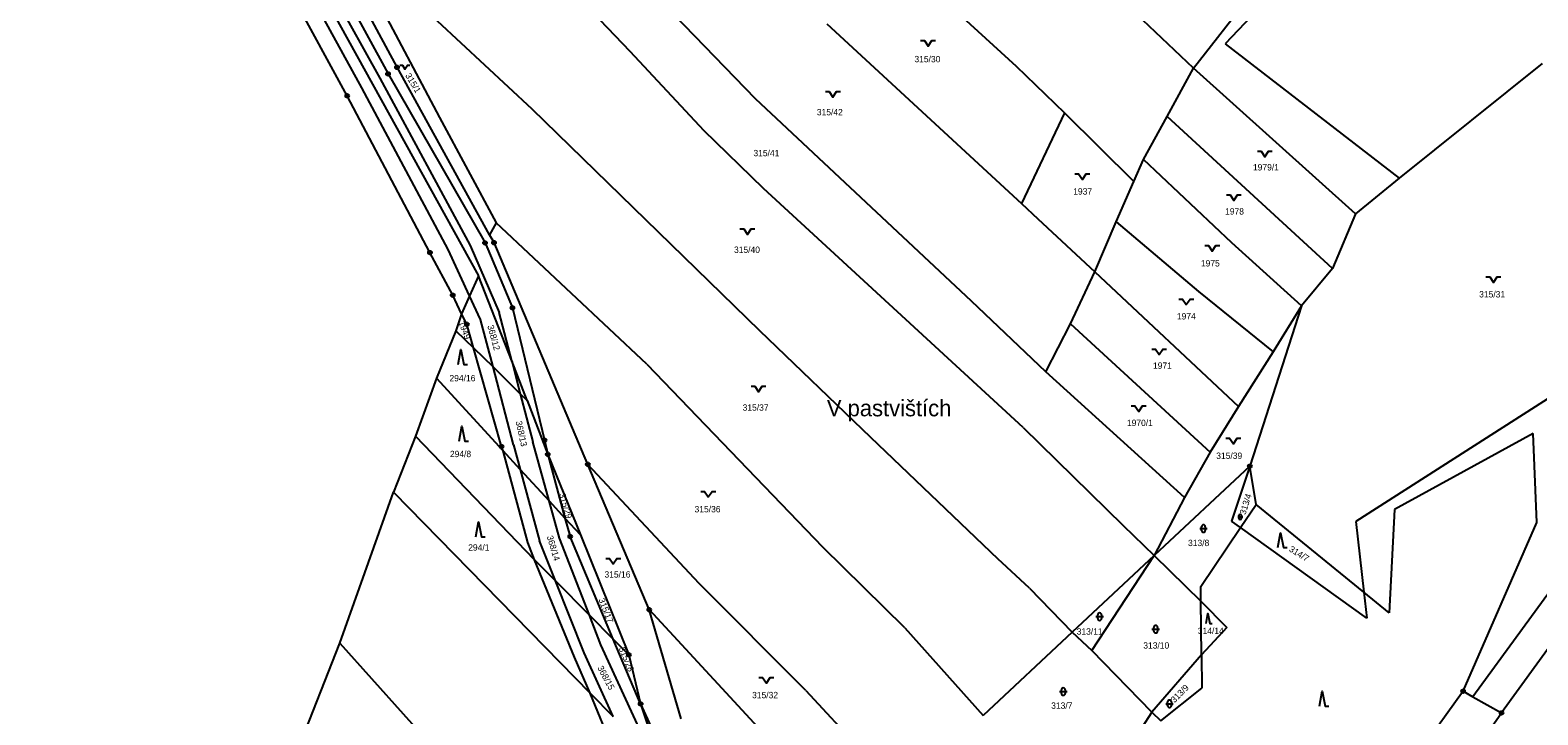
# Model space of a CAD drawing. Extents: x -762263 to -760336, y -1154405 to -1152076.
# Drawn here: x -761266.3 to -760862.4, y -1153501.2 to -1153317.8 of the extents above; entities that cross this region are included whole.
import ezdxf

# ---------------------------------------------------------------- set-up
doc = ezdxf.new("R2010")
doc.units = 0
for name, color, linetype in [('Vrstva 1', 7, 'Continuous'), ('Vrstva 15', 7, 'Continuous'), ('Vrstva 18', 7, 'Continuous'), ('Vrstva 24', 7, 'Continuous'), ('Vrstva 25', 7, 'Continuous'), ('Vrstva 4', 7, 'Continuous'), ('Vrstva 6', 7, 'Continuous')]:
    doc.layers.add(name, color=color, linetype=linetype)

msp = doc.modelspace()

# ---------------------------------------------------------------- linework, layer by layer
at = {"layer": 'Vrstva 1'}
for p, q in [((-761266.33, -1153166.38), (-761146.19, -1153383.6)), ((-761181.37, -1153335.36), (-761215.48, -1153272.86)), ((-761168.04, -1153327.74), (-761178.87, -1153307.53)), ((-761181.49, -1153309.12), (-761170.44, -1153329.52)), ((-760742.25, -1153321.15), (-760872.1, -1153500.69)), ((-761143.22, -1153372.6), (-761168.04, -1153327.74)), ((-761170.44, -1153329.52), (-761144.46, -1153374.78)), ((-761159.21, -1153377.37), (-761181.37, -1153335.36)), ((-761144.46, -1153374.78), (-761137.12, -1153392.18)), ((-761142.05, -1153374.72), (-761143.22, -1153372.6)), ((-761116.92, -1153434.11), (-761142.05, -1153374.72)), ((-761153.12, -1153388.8), (-761159.21, -1153377.37)), ((-761146.19, -1153383.6), (-761148.59, -1153388.96)), ((-761137.3, -1153406.37), (-761146.19, -1153383.6)), ((-761150.75, -1153393.78), (-761153.12, -1153388.8)), ((-761148.59, -1153388.96), (-761150.75, -1153393.78)), ((-761137.12, -1153392.18), (-761128.5, -1153427.63)), ((-761149.31, -1153396.6), (-761150.75, -1153393.78)), ((-761147.54, -1153402.91), (-761149.31, -1153396.6)), ((-761140.04, -1153429.35), (-761147.54, -1153402.91)), ((-761147.54, -1153402.91), (-761142.31, -1153408.03)), ((-761142.31, -1153408.03), (-761135.01, -1153415.18)), ((-761133.14, -1153417.01), (-761137.3, -1153406.37)), ((-761135.01, -1153415.18), (-761133.14, -1153417.01)), ((-761133.14, -1153417.01), (-761127.65, -1153431.43)), ((-761128.5, -1153427.63), (-761127.65, -1153431.43)), ((-760863.64, -1153425.86), (-760900.79, -1153446.25)), ((-760862.66, -1153449.7), (-760863.64, -1153425.86)), ((-761139.6, -1153430.49), (-761140.04, -1153429.35)), ((-761132.95, -1153455.07), (-761139.6, -1153430.49)), ((-761135, -1153435.48), (-761139.6, -1153430.49)), ((-761127.65, -1153431.43), (-761118.89, -1153453)), ((-761127.65, -1153431.43), (-761123.08, -1153448.52)), ((-761135, -1153435.48), (-761127.26, -1153443.9)), ((-761100.45, -1153473.04), (-761116.92, -1153434.11)), ((-760939.54, -1153434.62), (-760965.13, -1153458.53)), ((-760937.83, -1153444.85), (-760939.54, -1153434.62)), ((-761127.26, -1153443.9), (-761123.08, -1153448.52)), ((-760942.02, -1153451.05), (-760937.83, -1153444.85)), ((-760908.96, -1153468.39), (-760937.83, -1153444.85)), ((-761123.08, -1153448.52), (-761118.89, -1153453)), ((-761123.08, -1153448.52), (-761121.63, -1153453.44)), ((-760900.79, -1153446.25), (-760902.22, -1153473.89)), ((-761118.89, -1153453), (-761105.92, -1153485.15)), ((-760952.7, -1153466.84), (-760942.02, -1153451.05)), ((-760882.41, -1153494.9), (-760862.66, -1153449.7)), ((-761131.17, -1153459.68), (-761132.95, -1153455.07)), ((-761110.1, -1153480.92), (-761121.63, -1153453.44)), ((-761120.45, -1153485.8), (-761131.17, -1153459.68)), ((-761131.17, -1153459.68), (-761125.55, -1153465.35)), ((-760965.13, -1153458.53), (-760987.13, -1153479.09)), ((-761116.47, -1153474.5), (-761125.55, -1153465.35)), ((-760952.65, -1153470.8), (-760952.7, -1153466.84)), ((-760902.22, -1153473.89), (-760908.96, -1153468.39)), ((-761091.93, -1153502.27), (-761100.45, -1153473.04)), ((-760952.48, -1153485.18), (-760952.65, -1153470.8)), ((-761110.1, -1153480.92), (-761116.47, -1153474.5)), ((-761110.1, -1153480.92), (-761105.92, -1153485.15)), ((-761102.76, -1153498.28), (-761110.1, -1153480.92)), ((-760987.13, -1153479.09), (-761010.99, -1153501.39)), ((-761105.92, -1153485.15), (-761102.76, -1153498.28)), ((-760952.48, -1153485.18), (-760952.38, -1153494.09)), ((-761116.32, -1153495.42), (-761120.45, -1153485.8)), ((-761105.15, -1153522.27), (-761116.32, -1153495.42)), ((-761116.32, -1153495.42), (-761110.14, -1153501.67)), ((-760963.41, -1153502.81), (-760952.38, -1153494.09)), ((-760882.41, -1153494.9), (-760919.31, -1153546.23)), ((-760882.41, -1153494.9), (-760879.76, -1153496.39)), ((-760879.76, -1153496.39), (-760872.1, -1153500.69)), ((-761102.76, -1153498.28), (-761097.38, -1153514.59)), ((-761102.76, -1153498.28), (-761093.48, -1153518.8)), ((-760904.22, -1153546.18), (-760872.1, -1153500.69))]:
    msp.add_line(p, q, dxfattribs=at)
at = {"layer": 'Vrstva 24'}
for centre, radius in [((-761168.04, -1153327.74), 0.5), ((-761168.04, -1153327.74), 0.1), ((-761170.44, -1153329.52), 0.5), ((-761170.44, -1153329.52), 0.1), ((-761181.37, -1153335.36), 0.5), ((-761181.37, -1153335.36), 0.1), ((-761144.46, -1153374.78), 0.5), ((-761144.46, -1153374.78), 0.1), ((-761142.05, -1153374.72), 0.5), ((-761142.05, -1153374.72), 0.1), ((-761159.21, -1153377.37), 0.5), ((-761159.21, -1153377.37), 0.1), ((-761153.12, -1153388.8), 0.5), ((-761153.12, -1153388.8), 0.1), ((-761137.12, -1153392.18), 0.5), ((-761137.12, -1153392.18), 0.1), ((-761149.31, -1153396.6), 0.5), ((-761149.31, -1153396.6), 0.1), ((-761140.04, -1153429.35), 0.5), ((-761128.5, -1153427.63), 0.5), ((-761128.5, -1153427.63), 0.1), ((-761140.04, -1153429.35), 0.1), ((-761127.65, -1153431.43), 0.5), ((-761127.65, -1153431.43), 0.1), ((-761116.92, -1153434.11), 0.5), ((-761116.92, -1153434.11), 0.1), ((-760939.54, -1153434.62), 0.5), ((-760939.54, -1153434.62), 0.1), ((-761121.63, -1153453.44), 0.5), ((-761121.63, -1153453.44), 0.1), ((-761100.45, -1153473.04), 0.5), ((-761100.45, -1153473.04), 0.1), ((-761105.92, -1153485.15), 0.5), ((-761105.92, -1153485.15), 0.1), ((-760882.41, -1153494.9), 0.5), ((-760882.41, -1153494.9), 0.1), ((-761102.76, -1153498.28), 0.5), ((-761102.76, -1153498.28), 0.1), ((-760872.1, -1153500.69), 0.5), ((-760872.1, -1153500.69), 0.1)]:
    msp.add_circle(centre, radius, dxfattribs=at)
at = {"layer": 'Vrstva 25'}
for p, q in [((-760942.8, -1153448.18), (-760941.46, -1153448.18)), ((-760942.465, -1153448.515), (-760942.465, -1153447.845)), ((-760941.795, -1153447.845), (-760941.795, -1153448.515)), ((-760952.98, -1153451.31), (-760950.98, -1153451.31)), ((-760952.48, -1153451.81), (-760952.48, -1153450.81)), ((-760951.48, -1153450.81), (-760951.48, -1153451.81)), ((-760980.78, -1153474.91), (-760978.78, -1153474.91)), ((-760980.28, -1153475.41), (-760980.28, -1153474.41)), ((-760979.28, -1153474.41), (-760979.28, -1153475.41)), ((-760965.76, -1153478.28), (-760963.76, -1153478.28)), ((-760965.26, -1153478.78), (-760965.26, -1153477.78)), ((-760964.26, -1153477.78), (-760964.26, -1153478.78)), ((-760990.52, -1153494.99), (-760988.52, -1153494.99)), ((-760990.02, -1153495.49), (-760990.02, -1153494.49)), ((-760989.02, -1153494.49), (-760989.02, -1153495.49)), ((-760962.07, -1153498.25), (-760960.07, -1153498.25)), ((-760961.57, -1153498.75), (-760961.57, -1153497.75)), ((-760960.57, -1153497.75), (-760960.57, -1153498.75))]:
    msp.add_line(p, q, dxfattribs=at)
for points in [[(-761027.75, -1153320.58), (-761026.75, -1153320.58), (-761025.75, -1153322.08), (-761024.75, -1153320.58), (-761023.75, -1153320.58)], [(-761167.28, -1153327.205), (-761166.61, -1153327.205), (-761165.94, -1153328.21), (-761165.27, -1153327.205), (-761164.6, -1153327.205)], [(-761053.25, -1153334.23), (-761052.25, -1153334.23), (-761051.25, -1153335.73), (-761050.25, -1153334.23), (-761049.25, -1153334.23)], [(-760937.53, -1153350.22), (-760936.53, -1153350.22), (-760935.53, -1153351.72), (-760934.53, -1153350.22), (-760933.53, -1153350.22)], [(-760986.41, -1153356.27), (-760985.41, -1153356.27), (-760984.41, -1153357.77), (-760983.41, -1153356.27), (-760982.41, -1153356.27)], [(-760945.82, -1153361.94), (-760944.82, -1153361.94), (-760943.82, -1153363.44), (-760942.82, -1153361.94), (-760941.82, -1153361.94)], [(-761076.15, -1153371.05), (-761075.15, -1153371.05), (-761074.15, -1153372.55), (-761073.15, -1153371.05), (-761072.15, -1153371.05)], [(-760951.62, -1153375.52), (-760950.62, -1153375.52), (-760949.62, -1153377.02), (-760948.62, -1153375.52), (-760947.62, -1153375.52)], [(-760876.28, -1153383.9), (-760875.28, -1153383.9), (-760874.28, -1153385.4), (-760873.28, -1153383.9), (-760872.28, -1153383.9)], [(-760958.57, -1153389.83), (-760957.57, -1153389.83), (-760956.57, -1153391.33), (-760955.57, -1153389.83), (-760954.57, -1153389.83)], [(-761151.64, -1153407.38), (-761150.94, -1153403.38), (-761150.14, -1153407.38), (-761149.14, -1153407.38)], [(-760965.83, -1153403.21), (-760964.83, -1153403.21), (-760963.83, -1153404.71), (-760962.83, -1153403.21), (-760961.83, -1153403.21)], [(-761073.19, -1153413.16), (-761072.19, -1153413.16), (-761071.19, -1153414.66), (-761070.19, -1153413.16), (-761069.19, -1153413.16)], [(-760971.32, -1153418.45), (-760970.32, -1153418.45), (-760969.32, -1153419.95), (-760968.32, -1153418.45), (-760967.32, -1153418.45)], [(-761151.35, -1153427.88), (-761150.65, -1153423.88), (-761149.85, -1153427.88), (-761148.85, -1153427.88)], [(-760945.95, -1153427.08), (-760944.95, -1153427.08), (-760943.95, -1153428.58), (-760942.95, -1153427.08), (-760941.95, -1153427.08)], [(-761086.63, -1153441.34), (-761085.63, -1153441.34), (-761084.63, -1153442.84), (-761083.63, -1153441.34), (-761082.63, -1153441.34)], [(-761146.93, -1153453.53), (-761146.23, -1153449.53), (-761145.43, -1153453.53), (-761144.43, -1153453.53)], [(-760932, -1153456.43), (-760931.3, -1153452.43), (-760930.5, -1153456.43), (-760929.5, -1153456.43)], [(-761112.11, -1153459.3), (-761111.11, -1153459.3), (-761110.11, -1153460.8), (-761109.11, -1153459.3), (-761108.11, -1153459.3)], [(-760951.269, -1153476.74), (-760950.8, -1153474.06), (-760950.264, -1153476.74), (-760949.594, -1153476.74)], [(-761071.08, -1153491.2), (-761070.08, -1153491.2), (-761069.08, -1153492.7), (-761068.08, -1153491.2), (-761067.08, -1153491.2)], [(-760920.86, -1153498.86), (-760920.16, -1153494.86), (-760919.36, -1153498.86), (-760918.36, -1153498.86)]]:
    msp.add_lwpolyline(points, dxfattribs=at)
for centre, radius, start, end in [((-760942.13, -1153447.845), 0.335, 0, 180), ((-760942.13, -1153448.515), 0.335, 180, 0), ((-760951.98, -1153450.81), 0.5, 0, 180), ((-760951.98, -1153451.81), 0.5, 180, 0), ((-760979.78, -1153474.41), 0.5, 0, 180), ((-760979.78, -1153475.41), 0.5, 180, 0), ((-760964.76, -1153477.78), 0.5, 0, 180), ((-760964.76, -1153478.78), 0.5, 180, 0), ((-760989.52, -1153494.49), 0.5, 0, 180), ((-760989.52, -1153495.49), 0.5, 180, 0), ((-760961.07, -1153497.75), 0.5, 0, 180), ((-760961.07, -1153498.75), 0.5, 180, 0)]:
    msp.add_arc(centre, radius, start, end, dxfattribs=at)
at = {"layer": 'Vrstva 4'}
for p, q in [((-761177.43, -1153333.26), (-761211.89, -1153270.67)), ((-761207.48, -1153267.98), (-761172.64, -1153330.69)), ((-761172.64, -1153330.69), (-761148.45, -1153375.48)), ((-761154.29, -1153376.51), (-761177.43, -1153333.26)), ((-761148.45, -1153375.48), (-761140.65, -1153393.46)), ((-761148.59, -1153388.96), (-761154.29, -1153376.51)), ((-761145.69, -1153395.29), (-761148.59, -1153388.96)), ((-761142.31, -1153408.03), (-761145.69, -1153395.29)), ((-761137.3, -1153406.37), (-761140.65, -1153393.46)), ((-761136.79, -1153428.87), (-761142.31, -1153408.03)), ((-761137.3, -1153406.37), (-761135.01, -1153415.18)), ((-761135.01, -1153415.18), (-761131.65, -1153428.1)), ((-761127.26, -1153443.9), (-761131.65, -1153428.1)), ((-761136.79, -1153428.87), (-761135, -1153435.48)), ((-761135, -1153435.48), (-761129.84, -1153454.62)), ((-761124.5, -1153453.85), (-761127.26, -1153443.9)), ((-761125.55, -1153465.35), (-761129.84, -1153454.62)), ((-761116.47, -1153474.5), (-761124.5, -1153453.85)), ((-761117.86, -1153484.57), (-761125.55, -1153465.35)), ((-761113.39, -1153482.44), (-761116.47, -1153474.5)), ((-761110.14, -1153501.67), (-761117.86, -1153484.57)), ((-761099.65, -1153512.3), (-761113.39, -1153482.44))]:
    msp.add_line(p, q, dxfattribs=at)
at = {"layer": 'Vrstva 6'}
for p, q in [((-761142.21, -1153285.24), (-761105.65, -1153323.41)), ((-760910.51, -1153283.85), (-760946.11, -1153321.43)), ((-761034.57, -1153297.77), (-761002.14, -1153327.46)), ((-761175.56, -1153305.52), (-761156.64, -1153341.17)), ((-760954.6, -1153327.94), (-760979.45, -1153304.44)), ((-761163.61, -1153309.3), (-761131.94, -1153338.85)), ((-761072, -1153336.15), (-761096.46, -1153310.9)), ((-760954.6, -1153327.94), (-760939.21, -1153308.16)), ((-761052.85, -1153316.07), (-761000.75, -1153364.24)), ((-761105.65, -1153323.41), (-761085.87, -1153344.66)), ((-760946.11, -1153321.43), (-760899.55, -1153357.45)), ((-761002.14, -1153327.46), (-760989.24, -1153339.94)), ((-760861.26, -1153326.74), (-760899.55, -1153357.45)), ((-760961.71, -1153340.88), (-760954.6, -1153327.94)), ((-760911.27, -1153367.04), (-760954.6, -1153327.94)), ((-761131.94, -1153338.85), (-761070.93, -1153398.23)), ((-761014.09, -1153390.41), (-761072, -1153336.15)), ((-760989.24, -1153339.94), (-761000.75, -1153364.24)), ((-760989.24, -1153339.94), (-760970.59, -1153358.33)), ((-761156.64, -1153341.17), (-761141.44, -1153369.44)), ((-760968.03, -1153352.42), (-760961.71, -1153340.88)), ((-760917.43, -1153381.65), (-760961.71, -1153340.88)), ((-761069.82, -1153360.2), (-761085.87, -1153344.66)), ((-760970.59, -1153358.33), (-760968.03, -1153352.42)), ((-760944.34, -1153374.75), (-760968.03, -1153352.42)), ((-760975.36, -1153369.14), (-760970.59, -1153358.33)), ((-760899.55, -1153357.45), (-760911.27, -1153367.04)), ((-761000.3, -1153424.26), (-761069.82, -1153360.2)), ((-761000.75, -1153364.24), (-760996.34, -1153368.33)), ((-760911.27, -1153367.04), (-760917.43, -1153381.65)), ((-761141.44, -1153369.44), (-761143.22, -1153372.6)), ((-761101.13, -1153407.27), (-761141.44, -1153369.44)), ((-760996.34, -1153368.33), (-760981.06, -1153382.5)), ((-760981.06, -1153382.5), (-760975.36, -1153369.14)), ((-760975.36, -1153369.14), (-760953.26, -1153387.77)), ((-760789.66, -1153371.61), (-760911.11, -1153449.42)), ((-760925.74, -1153391.62), (-760944.34, -1153374.75)), ((-760987.58, -1153396.5), (-760981.06, -1153382.5)), ((-760981.06, -1153382.5), (-760942.59, -1153418.63)), ((-760917.43, -1153381.65), (-760925.74, -1153391.62)), ((-760953.26, -1153387.77), (-760933.3, -1153403.94)), ((-760994.19, -1153409.36), (-761014.09, -1153390.41)), ((-760925.74, -1153391.62), (-760939.54, -1153434.62)), ((-760925.74, -1153391.62), (-760933.3, -1153403.94)), ((-761150.75, -1153393.78), (-761152.24, -1153398.37)), ((-760994.19, -1153409.36), (-760987.58, -1153396.5)), ((-760987.58, -1153396.5), (-760950.21, -1153430.82)), ((-761152.24, -1153398.37), (-761157.47, -1153411.01)), ((-761152.24, -1153398.37), (-761147.54, -1153402.91)), ((-761070.93, -1153398.23), (-761041.14, -1153426.87)), ((-760933.3, -1153403.94), (-760942.59, -1153418.63)), ((-761101.13, -1153407.27), (-761053.94, -1153456.26)), ((-761157.47, -1153411.01), (-761163.05, -1153426.58)), ((-761139.6, -1153430.49), (-761157.47, -1153411.01)), ((-760957.02, -1153443), (-760994.19, -1153409.36)), ((-760942.59, -1153418.63), (-760950.21, -1153430.82)), ((-761000.3, -1153424.26), (-760973.51, -1153450.47)), ((-761163.05, -1153426.58), (-761168.99, -1153441.57)), ((-761131.17, -1153459.68), (-761163.05, -1153426.58)), ((-761041.14, -1153426.87), (-761007.03, -1153459.46)), ((-760950.21, -1153430.82), (-760957.02, -1153443)), ((-761087.08, -1153466), (-761116.92, -1153434.11)), ((-760939.54, -1153434.62), (-760944.45, -1153449.31)), ((-761183.36, -1153481.98), (-761168.99, -1153441.57)), ((-761168.99, -1153441.57), (-761116.32, -1153495.42)), ((-760957.02, -1153443), (-760965.13, -1153458.53)), ((-760841.8, -1153444.25), (-760879.76, -1153496.39)), ((-760973.51, -1153450.47), (-760965.13, -1153458.53)), ((-760942.02, -1153451.05), (-760944.45, -1153449.31)), ((-760908.18, -1153475.3), (-760942.02, -1153451.05)), ((-760911.11, -1153449.42), (-760908.96, -1153468.39)), ((-761031.98, -1153477.92), (-761053.94, -1153456.26)), ((-760998.55, -1153467.29), (-761007.03, -1153459.46)), ((-760981.88, -1153483.99), (-760965.13, -1153458.53)), ((-760965.13, -1153458.53), (-760952.65, -1153470.8)), ((-761058.49, -1153494.72), (-761087.08, -1153466)), ((-760998.55, -1153467.29), (-760987.13, -1153479.09)), ((-760908.96, -1153468.39), (-760908.18, -1153475.3)), ((-761100.45, -1153473.04), (-761062.86, -1153513.72)), ((-760952.65, -1153470.8), (-760945.73, -1153477.84)), ((-761031.98, -1153477.92), (-761010.99, -1153501.39)), ((-760987.13, -1153479.09), (-760981.88, -1153483.99)), ((-760945.73, -1153477.84), (-760952.48, -1153485.18)), ((-761196.01, -1153514.22), (-761183.36, -1153481.98)), ((-761183.36, -1153481.98), (-761106.64, -1153567.61)), ((-760965.76, -1153500.49), (-760981.88, -1153483.99)), ((-760952.48, -1153485.18), (-760965.76, -1153500.49)), ((-761058.49, -1153494.72), (-761030.9, -1153524.45)), ((-760965.76, -1153500.49), (-760971.3, -1153509.04)), ((-760965.76, -1153500.49), (-760963.41, -1153502.81))]:
    msp.add_line(p, q, dxfattribs=at)

# ---------------------------------------------------------------- texts
at = {"layer": 'Vrstva 15'}
msp.add_text('V pastvištích', height=4.4, dxfattribs=at).set_placement((-761052.866, -1153421.24))
at = {"layer": 'Vrstva 18'}
for s, p in [('315/30', (-761029.402, -1153326.39)), ('315/42', (-761055.552, -1153340.6)), ('315/41', (-761072.54, -1153351.57)), ('1979/1', (-760938.706, -1153355.38)), ('1937', (-760986.862, -1153361.84)), ('1978', (-760946.175, -1153367.19)), ('315/40', (-761077.745, -1153377.46)), ('1975', (-760952.662, -1153381.1)), ('315/31', (-760878.097, -1153389.4)), ('1974', (-760959.085, -1153395.3)), ('1971', (-760965.487, -1153408.52)), ('294/16', (-761153.988, -1153411.87)), ('315/37', (-761075.435, -1153419.74)), ('1970/1', (-760972.473, -1153423.85)), ('294/8', (-761153.867, -1153432.18)), ('315/39', (-760948.545, -1153432.65)), ('315/36', (-761088.315, -1153446.97)), ('294/1', (-761148.959, -1153457.23)), ('313/8', (-760956.099, -1153456.01)), ('315/16', (-761112.453, -1153464.44)), ('313/11', (-760985.932, -1153479.73)), ('314/14', (-760953.473, -1153479.57)), ('313/10', (-760968.087, -1153483.47)), ('315/32', (-761072.899, -1153496.77)), ('313/7', (-760992.769, -1153499.6))]:
    msp.add_text(s, height=1.7, dxfattribs=at).set_placement(p)
for s, rotation, p in [('315/1', 300.91743, (-761165.905, -1153329.947)), ('1949', 290.37501, (-761151.599, -1153396.068)), ('368/12', 285.27569, (-761143.847, -1153397.029)), ('368/13', 282.46819, (-761136.279, -1153422.672)), ('315/29', 286.02053, (-761124.619, -1153442.113)), ('313/4', 72.53646, (-760940.718, -1153447.729)), ('368/14', 286.82267, (-761127.941, -1153453.457)), ('314/7', 328.36211, (-760929.197, -1153457.277)), ('315/17', 291.17715, (-761114.092, -1153470.338)), ('315/28', 292.72414, (-761108.686, -1153483.439)), ('368/15', 298.16724, (-761114.418, -1153488.619)), ('313/9', 44.97719, (-760959.736, -1153498.124))]:
    msp.add_text(s, height=1.7, rotation=rotation, dxfattribs=at).set_placement(p)

doc.saveas('drawing.dxf')
